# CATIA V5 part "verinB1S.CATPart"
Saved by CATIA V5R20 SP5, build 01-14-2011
Part number: verinB1S
Publications: "Droite.2", "Point.3", "Point.1"
Bounding box of the stored display mesh (mm): x 0 to 0, y -70 to 55, z 240 to 1175
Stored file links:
  U:\think motion\fin\verinB1S.CATPart
  U:\think motion\fin\squelette.CATProduct
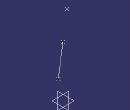
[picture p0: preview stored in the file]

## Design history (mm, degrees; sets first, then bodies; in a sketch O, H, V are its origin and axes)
Set1
  Point1: linked copy from another document
Set2
  Point2: type OnPlane, Support yz-plane, H -70, V 240, Direction (0, 1, 0)
  Line1: type PtPt, FirstPoint Point2, SecondPoint Point1, Support yz-plane
  Point3: type OnCurve, Support Line1, Length 500
  Line2: type PtPt, FirstPoint Point3, SecondPoint Point2
Body1 (main body)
